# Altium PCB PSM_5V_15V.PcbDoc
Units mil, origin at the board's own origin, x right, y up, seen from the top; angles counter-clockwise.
Board outline 1150 x 1300 mil, 2 copper layers (Top Layer, Bottom Layer), stack 62 mil thick; 19 components, 10 nets, 41 pads, 8 vias.
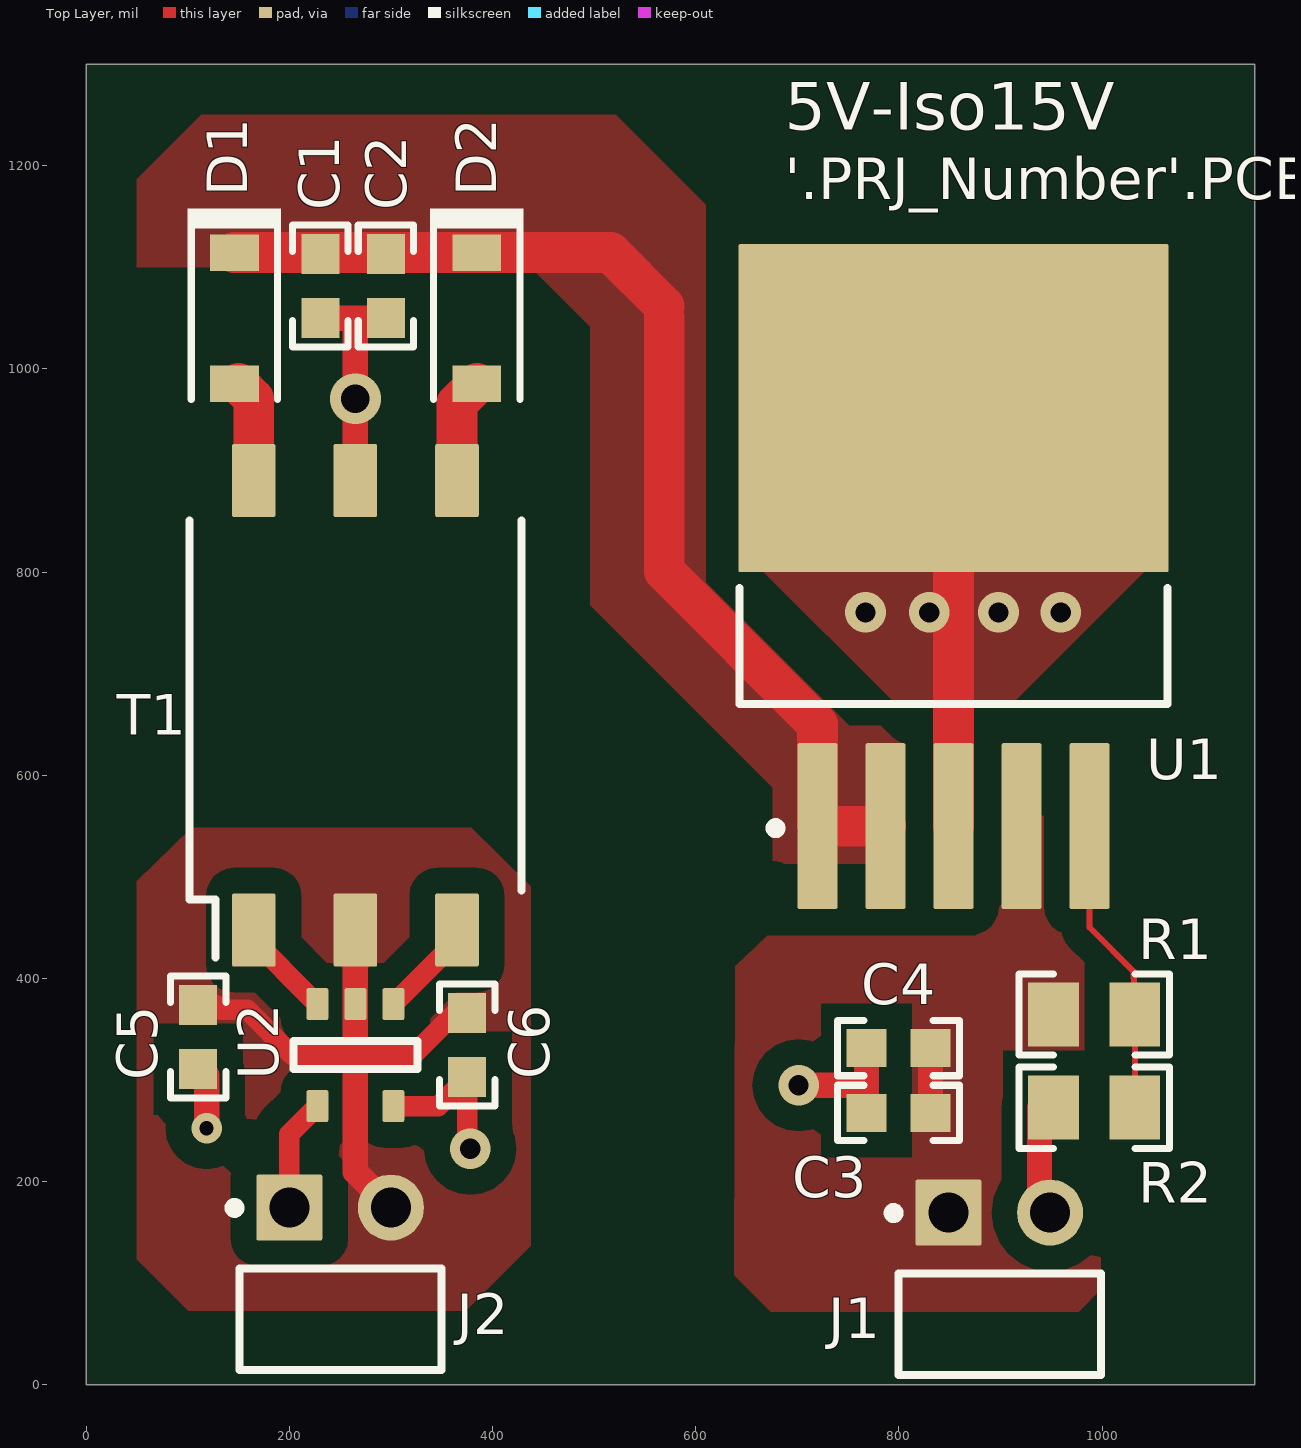
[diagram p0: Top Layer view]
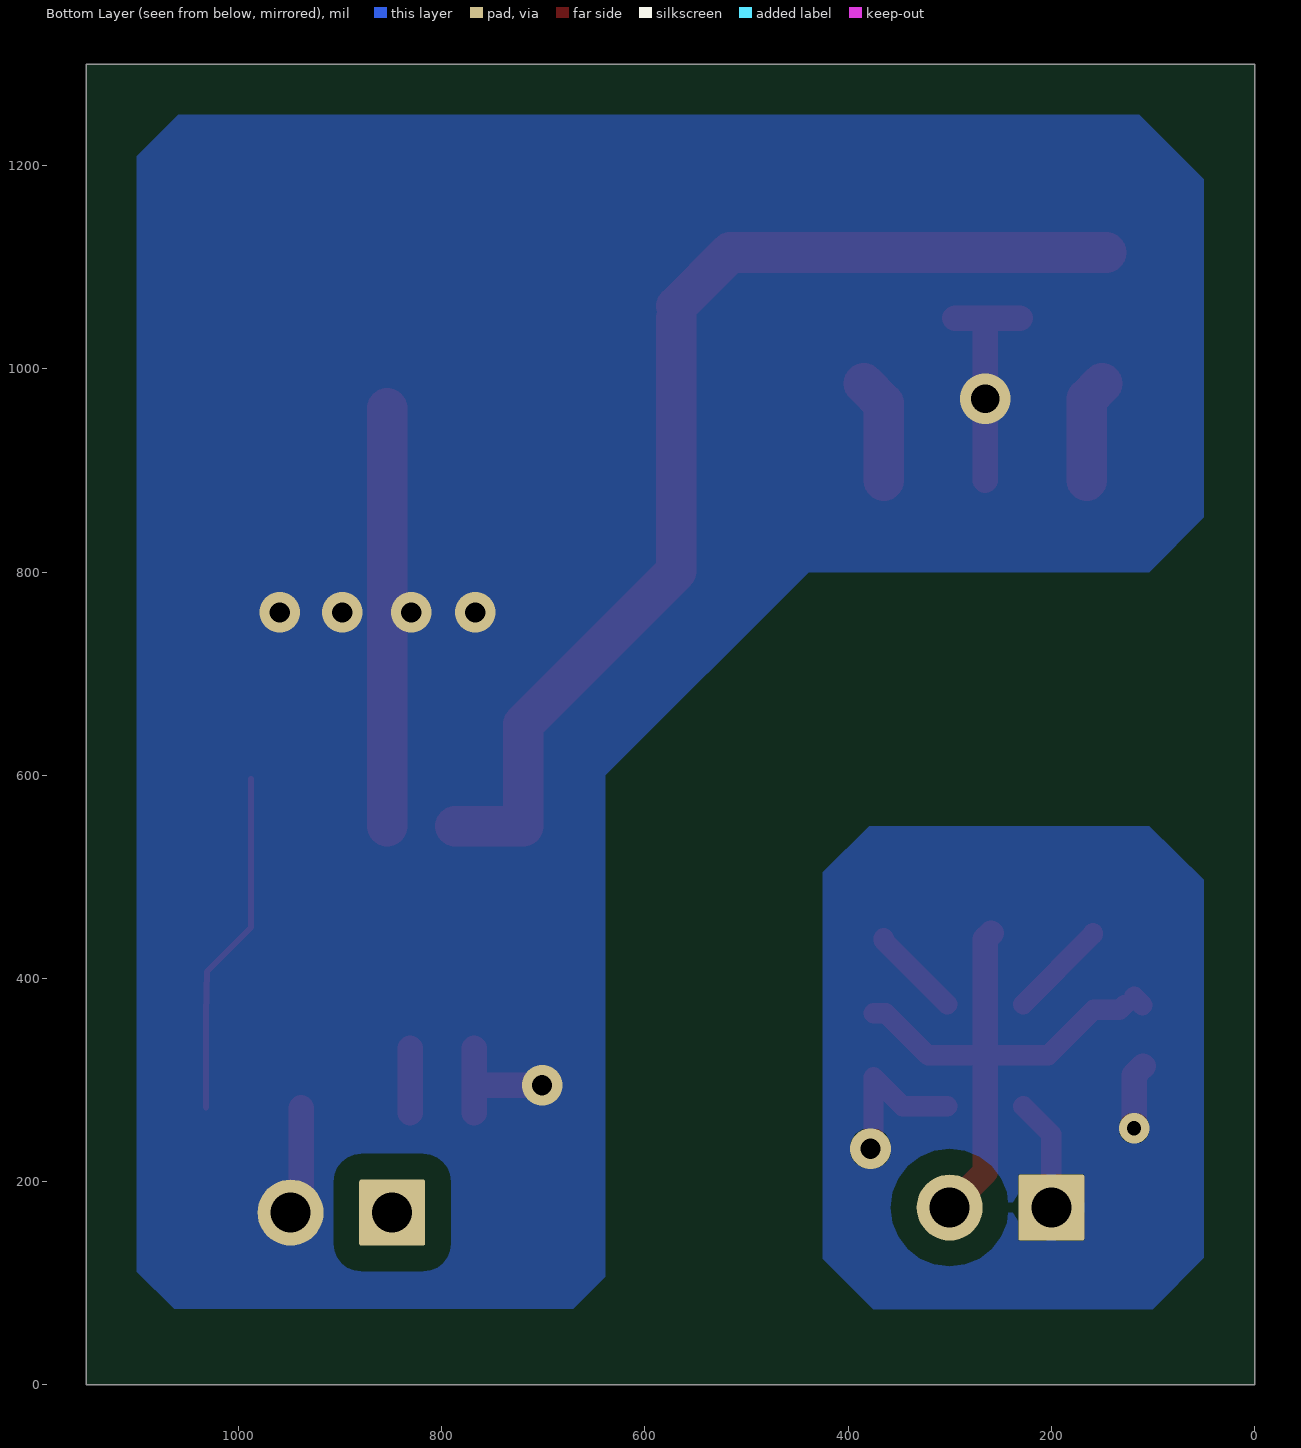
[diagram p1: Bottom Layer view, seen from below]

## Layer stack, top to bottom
Top Solder: solder mask 0.4, Solder Resist, Dk 3.5
Top Layer: signal copper 1.4
Dielectric1: core 59.2, FR-4, Dk 4.8
Bottom Layer: signal copper 1.4
Bottom Solder: solder mask 0.4, Solder Resist, Dk 3.5

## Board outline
0,0 1150,0 1150,1300 0,1300

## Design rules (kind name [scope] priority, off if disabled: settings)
AcuteAngle [All] p1: minimum=4.50000000000000E+0001 checktracksonly=FALSE
AssemblyTestPointUsage [All] p1: valid=2
BoardOutlineClearance BoardOutlineClearance_MountingHoles [OnCopper and InComponentClass('Mounting Holes')] p1: gap=39.37 ignorepadtopadclearanceinfootprint=FALSE
BoardOutlineClearance BoardOutlineClearance_Poly [OnCopper and IsPoly] p2: gap=25 ignorepadtopadclearanceinfootprint=FALSE
BoardOutlineClearance [OnCopper and Not InComponentClass('Logo') and not InComponentClass('FiducialMark') and not InRegion(1000,500,4000,800) and not InPoly] p3: gap=75 ignorepadtopadclearanceinfootprint=FALSE
Clearance Clearance_Keepouts [((IsTrack Or IsArc) And Not InPoly) And IsFree and IsKeepOut vs ((IsTrack Or IsArc) And Not InPoly) And IsFree and IsKeepOut] p1: gap=0 ignorepadtopadclearanceinfootprint=FALSE
Clearance Clearance_Poly [InPolygon] p2: gap=25 ignorepadtopadclearanceinfootprint=TRUE
Clearance Clearance_FiducialMark [IsKeepOut and InComponentClass('FiducialMark') vs IsPad and InComponentClass('FiducialMark')] p3: gap=0 ignorepadtopadclearanceinfootprint=FALSE
Clearance [All] p4: gap=7.87 ignorepadtopadclearanceinfootprint=TRUE
ComponentClearance ComponentClearance_MountingHoles_FiducialMarks [InComponentClass('Mounting Holes') vs InComponentClass('FiducialMark')] p1: gap=50 collisioncheckmode=3 verticalgap=10 showdistances=FALSE
ComponentClearance ComponentClearance_Shunt [InComponentClass('Header') vs InComponentClass('Shunt')] p2: gap=0 collisioncheckmode=3 verticalgap=0 showdistances=FALSE
ComponentClearance ComponentClearance_Logo [InComponentClass('Hardware')] p3: gap=20 collisioncheckmode=3 verticalgap=10 showdistances=FALSE
ComponentClearance ComponentClearance_ScrewToNut [(HasFootprint('NY PMS 440 0025 PH')) vs (HasFootprint('Keystone_1902C'))] p4: gap=5 collisioncheckmode=3 verticalgap=10 showdistances=FALSE
ComponentClearance ComponentClearance_MountingHoles [InComponentClass('Mounting Holes')] p5: gap=250 collisioncheckmode=3 verticalgap=100000 showdistances=FALSE
ComponentClearance ComponentClearance_SmallPassives [HasFootprint('0201*') or HasFootprint('0402*') or HasFootprint('0508') or HasFootprint('0603*') or HasFootprint('0612') or HasFootprint('0805*') or HasFootprint('0815*') or HasFootprint('0830*') or HasFootprint('1206*') or HasFootprint('1210*') or HasFootprint('1808*') or HasFootprint('1812*') or HasFootprint('1825*') or HasFootprint('2010*') or HasFootprint('2220*') or HasFootprint('2225*') or HasFootprint('2512*') or HasFootprint('2728*') or HasFootprint('3518*') vs HasFootprint('0201*') or HasFootprint('0402*') or HasFootprint('0508') or HasFootprint('0603*') or HasFootprint('0612') or HasFootprint('0805*') or HasFootprint('0815*') or HasFootprint('0830*') or HasFootprint('1206*') or HasFootprint('1210*') or HasFootprint('1808*') or HasFootprint('1812*') or HasFootprint('1825*') or HasFootprint('2010*') or HasFootprint('2220*') or HasFootprint('2225*') or HasFootprint('2512*') or HasFootprint('2728*') or HasFootprint('3518*')] p6: gap=14.96 collisioncheckmode=3 verticalgap=10 showdistances=FALSE
ComponentClearance ComponentClearance_THtoSMT [IsThruComponent vs IsSMTComponent] p7: gap=40 collisioncheckmode=3 verticalgap=30 showdistances=FALSE
ComponentClearance ComponentClearance_THtoTH [IsThruComponent vs IsThruComponent] p8: gap=30 collisioncheckmode=3 verticalgap=30 showdistances=FALSE
ComponentClearance [not InComponent('Logo2')] p9: gap=30 collisioncheckmode=3 verticalgap=10 showdistances=FALSE
DiffPairsRouting [All] p1: maxlimit=100 minlimit=10 mostfreqgap=10 toplayer_minwidth=15 toplayer_maxwidth=15 toplayer_prefwidth=15 bottomlayer_minwidth=15 bottomlayer_maxwidth=15 bottomlayer_prefwidth=15 maxuncoupledlength=1000
FabricationTestPointUsage TestPointUsage [All] p1: valid=2 allowmultiple=FALSE
FabricationTestpoint Testpoint [All] p1: side=3 testpointundercomponent=TRUE minsize=40 maxsize=100 preferedsize=60 minholesize=0 maxholesize=40 preferedholesize=32 testpointgrid=1 allowsidetop=TRUE allowsidebottom=TRUE usegrid=TRUE gridtolerance=0.01
FanoutControl Fanout_LCC [IsLCC] p1: bgadir=Out bgaviamode=Centered fanoutstyle=Auto fanoutdirection=Alternating viagrid=1 // Fanout_LCC (Default Rule)
FanoutControl Fanout_BGA [IsBGA] p2: bgadir=Out bgaviamode=Centered fanoutstyle=Auto fanoutdirection=Alternating viagrid=1 // Fanout_BGA (Default Rule)
FanoutControl Fanout_Default [All] p4: bgadir=Out bgaviamode=Centered fanoutstyle=Auto fanoutdirection=Alternating viagrid=1 // Fanout_Default (Default Rule)
FanoutControl Fanout_Small [(CompPinCount < 5)] p5: bgadir=Out bgaviamode=Centered fanoutstyle=Auto fanoutdirection=OutThenIn viagrid=1 // Fanout_Small (Default Rule)
HoleSize [All] p1: absolutevalues=TRUE maxlimit=251 minlimit=7.87 maxpercent=80.000 minpercent=20.000
MinimumAnnularRing MinimumAnnularRing_ThermalPadVias [IsVia and InAnyComponent] p1: minimumring=5.91
MinimumAnnularRing [All] p2: minimumring=7.87
MinimumSolderMaskSliver MinimumSolderMaskSliver_Logo [InComponentClass('Logo') vs InComponentClass('Logo')] p1: minsoldermaskwidth=0.7
MinimumSolderMaskSliver [All] p2: minsoldermaskwidth=3.94
PlaneConnect [All] p1: planeconnectstyle=Relief reliefexpansion=10 reliefentries=4 reliefconductorwidth=10 reliefairgap=10
PolygonConnect [All] p1: connectstyle=Direct reliefconductorwidth=10 reliefentries=4 polygonreliefangle="90 Angle" airgapwidth=10
RoutingVias ThermalPadVias [IsVia and InAnyComponent] p1: holewidth=7.87 width=19.68 viastyle="Through Hole" minholewidth=7.87 minwidth=19.68 maxholewidth=12.99 maxwidth=23.62
RoutingVias [All] p2: holewidth=16 width=34 viastyle="Through Hole" minholewidth=7.87 minwidth=26 maxholewidth=40 maxwidth=65
SilkToBoardRegionClearance [Not ((IsComment or IsDesignator) And (Hide <> 'False')) and not InRegion(1000,500,4000,800)] p1:
SilkToSilkClearance SilkToSilkClearance_Pb-FreeLogo [(HasFootprint('Pb-Free_Overlay_Medium') OR HasFootprint('Pb-Free_Overlay_Small')) vs (HasFootprint('Pb-Free_Overlay_Medium') OR HasFootprint('Pb-Free_Overlay_Small'))] p1: silktosilkclearance=0
SilkToSilkClearance [All] p2: silktosilkclearance=3.94
SilkToSolderMaskClearance SilkToComponentPadClearance [(IsPad or IsFill or IsRegion) and InAnycomponent and not ((InComponent('D1') OR InComponent('D2')))] p1: minsilkscreentomaskgap=5 clearancetoexposedcopper=TRUE
SilkToSolderMaskClearance "Silk to Solder Mask Opening" [not ((InComponent('D1') OR InComponent('D2')))] p2: minsilkscreentomaskgap=3.94 clearancetoexposedcopper=FALSE
SolderMaskExpansion [All] p1: expansion=1.97
UnRoutedNet [All] p1: checkbadconnections=TRUE
Width [All] p1: maxlimit=100 minlimit=6 preferedwidth=10 checkconnectedcopper=TRUE
14 further rules are at their usual default settings.

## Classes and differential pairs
component class AssemblyNote: ZZ1 ZZ2 ZZ3 ZZ4

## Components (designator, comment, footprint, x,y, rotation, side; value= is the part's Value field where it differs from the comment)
C1 "C1608X5R1E106M080AC" 0603 230.53,1081.5 r90 top value=10uF
C2 "GCM188R71H103KA37D" 0603 295,1081.56 r270 top value=0.01uF
C3 "C1608X5R1E106M080AC" 0603 799.55,267.72 r180 top value=10uF
C4 "GCM188R71H103KA37D" 0603 799.55,331.57 r180 top value=0.01uF
C5 "GCM188R71C105KA64D" 0603 110.26,342.32 r270 top value=1uF
C6 "CGA3E2X7R1H104K080AA" 0603 375,334.45 r270 top value=0.1uF
D1 "MBR0540T1G" SOD-123 145.93,1050.07 r270 top value=40V
D2 "MBR0540T1G" SOD-123 384.53,1050.07 r270 top value=40V
J1 "TSW-102-08-G-S-RA" TSW-102-08-G-S-RA 898.72,169.61 r0 top
J2 "TSW-102-08-G-S-RA" TSW-102-08-G-S-RA 250,174.61 r0 top
R1 "ERJ-6ENF1152V" 0805_HV 992.19,364.55 r180 top value=11.5k
R2 "ERJ-6ENF1021V" 0805_HV 992.19,272.87 r0 top value=1.02k
T1 "750316818" Wurth_750316029 265.01,668.97 r90 top value=94uH
U1 "TL1963AQKTTRQ1" KTT0005A_N 853.72,796.06 r90 top
U2 "SN6501QDBVRQ1" DBV0005A_L 265.01,324.61 r270 top
ZZ1 "This Assembly Note is for PCB labels only" AssemblyNoteLabel 60,1663 r0 top
ZZ2 "These assemblies are ESD sensitive, ESD precautions shall be observed." AssemblyNote 60,1554.11 r0 top
ZZ3 "These assemblies must be clean and free from flux and all contaminants. Use of no clean flux is not acceptable." AssemblyNote 60,1465.56 r0 top
ZZ4 "These assemblies must comply with workmanship standards IPC-A-610 Class 2, unless otherwise specified." AssemblyNote 60,1377 r0 top

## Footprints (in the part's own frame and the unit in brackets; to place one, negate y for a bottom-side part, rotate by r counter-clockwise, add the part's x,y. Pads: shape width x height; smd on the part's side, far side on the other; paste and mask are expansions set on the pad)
0603 [mm] "0603 from SM-752 data"
  rect 1x0.95 smd: 1(-0.8,0) 2(0.8,0)
  silkscreen extent -1.52,-0.69 1.52,0.69, body extent -0.87,-0.47 0.87,0.47, height 1
0805_HV [mil] "0805 with 30mil clearance between pads"
  rect 50x63 smd: 1(-40,0) 2(40,0)
  silkscreen extent -74,-40 74,40, body extent -43,-29 43,29, height 57
AssemblyNote [mil] "Assembly Note"
AssemblyNoteLabel [mil] "Assembly Note for PCB Labels"
DBV0005A_L [mm] "SOT23, 5-Leads, Body 2.9x1.6mm, Pitch 0.95mm, Lead Span 2.8mm, IPC High Density"
  rrect18% 0.8x0.55 smd: 1(-1.275,0.95) 2(-1.275,0) 3(-1.275,-0.95) 4(1.275,-0.95) 5(1.275,0.95)
  silkscreen extent -0.35,-1.55 0.35,1.55, body extent -1.42,-1.46 1.42,1.46, height 1.09
KTT0005A_N [mm] "D2-PAK, 6-Leads, Body 8.9x10.2mm, Pitch 1.7mm, Lead Span 15.2mm, IPC Medium Density"
  rrect10% 4.15x1 smd: 1(-6.25,3.4) 2(-6.25,1.7) 3(-6.25,0) 4(-6.25,-1.7) 5(-6.25,-3.4)
  rrect1% 8.2x10.75 smd: 6(4.2,0)
  silkscreen extent -6.42,-5.35 -0.3,5.35, body extent -7.63,-5.08 7.63,5.08, height 4.83
SOD-123 [mm] "On Semi recommended land pattern"
  rect 0.915x1.22 smd: 1(-1.637,0) 2(1.637,0)
  silkscreen extent -2.74,-1.17 2.03,1.17, body extent -1.93,-0.9 1.93,0.9, height 1.35
TSW-102-08-G-S-RA [mm] "Samtec Right Angle Header"
  rrect6% 1.65x1.65 hole 1: 1(-1.27,0)
  round 1.65 hole 1: 2(1.27,0)
  silkscreen extent -2.76,-4.06 2.54,0.11, body extent -2.54,-9.91 2.54,0.32, height 3.05
Wurth_750316029 [mm] "SMD, 6-Leads, Body 9.25x8.3mm, Pitch 2.54mm"
  rrect9% 1.83x1.09 smd: 1(-5.62,2.54) 2(-5.62,0) 3(-5.62,-2.54) 4(5.62,-2.54) 5(5.62,0) 6(5.62,2.54)
  silkscreen extent -6.3,-4.15 4.62,4.15, body extent -4.62,-4.15 4.62,4.15, height 4.11

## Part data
C1 C3: library part CMP-0007007-5, "CAP, CERM, 10 uF, 25 V, +/- 20%, X5R, 0603", Cap_Case=0603, Manufacturer=TDK, Supplier Part Number 1=445-9015-1-ND, TempCo=X5R, Tolerance_%=20%, Value1="0.004639 ohm", Value2=25V, ValueDisplayed=10uF
C2 C4: library part CMP-0007143-4, "CAP, CERM, 0.01 uF, 50 V, +/- 10%, X7R, AEC-Q200 Grade 1, 0603", Cap_Case=0603, Manufacturer=MuRata, Supplier Part Number 1=490-4778-1-ND, TempCo=X7R, Tolerance_%=10%, Value1=Unknown, Value2=50V, ValueDisplayed=0.01uF
C5: library part CMP-0007136-5, "CAP, CERM, 1 uF, 16 V, +/- 10%, X7R, AEC-Q200 Grade 1, 0603", Cap_Case=0603, Manufacturer=MuRata, Supplier Part Number 1=490-5241-6-ND, TempCo=X7R, Tolerance_%=10%, Value1=Unknown, Value2=16V, ValueDisplayed=1uF
C6: library part CMP-0007078-4, "CAP, CERM, 0.1 uF, 50 V, +/- 10%, X7R, AEC-Q200 Grade 1, 0603", Cap_Case=0603, Manufacturer=TDK, Supplier Part Number 1=445-5666-1-ND, TempCo=X7R, Tolerance_%=10%, Value1="0.0296 ohm", Value2=50V, ValueDisplayed=0.1uF
D1 D2: library part CMP-0028526-2, "Diode, Schottky, 40 V, 0.5 A, SOD-123", Manufacturer="ON Semiconductor", Value1=0.5A, Value2=0.51V
J1 J2: library part CMP-0055976-1, "Header, 100mil, 2x1, Gold, R/A, TH", Color=Black, Current_A=6.3A, Manufacturer=Samtec, Supplier Part Number 1=SAM1039-02-ND, Voltage_V=550V
R1: library part CMP-0021540-3, "RES, 11.5 k, 1%, 0.125 W, AEC-Q200 Grade 0, 0805", Manufacturer=Panasonic, Power_W=125mW, Supplier Part Number 1=P11.5KCCT-ND, TempCo="100 ppm/C", Tolerance_%=1%, Value2=0.125W, Value_Code=11k5, ValueDisplayed=11.5k
R2: library part CMP-0021523-3, "RES, 1.02 k, 1%, 0.125 W, AEC-Q200 Grade 0, 0805", Manufacturer=Panasonic, Power_W=125mW, Supplier Part Number 1=P1.02KCCT-ND, TempCo="100 ppm/C", Tolerance_%=1%, Value2=0.125W, Value_Code=1k02, ValueDisplayed=1.02k
T1: library part CMP-0067601-1, "Transformer, 94 uH, SMT", Manufacturer="Wurth Elektronik", ValueDisplayed=94µH
U1: library part CMP-0036893-1, "Single Output Fast Transient Response LDO, 1.5 A, Adjustable 1.21 to 20 V Output, 2.1 to 20 V Input, 5-pin DDPAK (KTT), -40 to 125 degC, Green (RoHS & no Sb/Br)", Manufacturer="Texas Instruments"
U2: library part CMP-0076093-1, "Automotive Low-Noise 350 mA, 410 kHz Transformer Driver, DBV0005A (SOT-23-5)", Alternate Manufacturer="Texas Instruments"
ZZ1: library part CMP-0003616-3
ZZ2: library part CMP-0077236-1
ZZ3: library part CMP-0077237-1
ZZ4: library part CMP-0077238-1

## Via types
v1: diameter 40, hole 20, Top Layer to Bottom Layer, 6 vias
v2: diameter 50, hole 28, Top Layer to Bottom Layer, 1 vias
v3: diameter 30, hole 14, Top Layer to Bottom Layer, 1 vias

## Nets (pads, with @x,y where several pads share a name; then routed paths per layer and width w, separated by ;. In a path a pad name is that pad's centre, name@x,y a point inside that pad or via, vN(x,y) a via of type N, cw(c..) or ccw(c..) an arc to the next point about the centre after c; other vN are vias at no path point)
5V: C5.1 C6.1 J2.2 T1.2 U2.2 | length 583
  Top Layer w20: C5.1 C5.1@118.53,382.09 ; C5.1@128.29,373.82 132.9,369.2 158.46,369.2 203.06,324.61 265.01,324.61 321.46,324.61 362.8,365.94 C6.1
  Top Layer w25: T1.2@259,444.74 265.01,438.74 U2.2 265.01,324.61 265.01,209.6 J2.2
15V: C3.1 C4.1 J1.1 R1.2 U1.4 | length 63.9
  Top Layer w25: C3.1 C4.1
DGND: C5.2 C6.2 J2.1 U2.4 U2.5 | length 332
  Top Layer w20: J2.1 200,246.81 U2.4 ; U2.5 346.46,274.41 C6.2 375,235.58 v1(378,232.58)
  Top Layer w25: C5.2@109.59,313.78 118.53,304.83 v3(118.53,252.72)
NetC1_2: C1.2 C2.1 D1.1 D2.1 U1.1 U1.2 | length 1074.5
  Top Layer w40: D1.1 D2.1 516.19,1114.53 569.03,1061.7 ; 569.03,1050.07 569.03,801.05 719.87,650.21 U1.1 U1.2
NetD1_2: D1.2 T1.6 | length 101.6
  Top Layer w40: D1.2@150,985.6 165.01,970.59 T1.6
NetD2_2: D2.2 T1.4 | length 103.5
  Top Layer w40: T1.4 365.01,966.07 D2.2
NetR1_1: R1.1 R2.2 U1.5 | length 341.4
  Top Layer w6: U1.5@987.58,596.19 U1.5 987.58,450.42 1031.11,406.89 R1.1 R2.2
NetT1_1: T1.1 U2.3 | length 98.4
  Top Layer w20: T1.1@159,444.74 159,443.4 U2.3
NetT1_3: T1.3 U2.1 | length 90.7
  Top Layer w20: U2.1 365.01,437.4 T1.3@365.01,439.54
RSLVR_GND: C1.1 C2.2 C3.2 C4.2 J1.2 R2.1 T1.5 U1.3 U1.6 | length 915.2
  Top Layer w25: T1.5 v2(265.01,970.59) 265.01,1047.21 267.8,1050 C1.1 230.6,1050.07 C2.2 ; v1(701.23,294.92) 760.64,294.92 767.53,301.8 767.79,302.07 768.05,301.8 ; C3.2 768.05,301.8 ; C4.2 768.05,301.8 ; R2.1@938.37,272.64 938.37,179.96 J1.2
  Top Layer w40: U1.3 U1.6
  other v1: 767.16,760.34 829.85,760.34 897.94,760.34 959.34,760.34

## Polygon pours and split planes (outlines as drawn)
RSLVR_GND on Bottom Layer "BOTTOM_LAYER_RSLVR_GND_P004" (solid, remove dead copper, pour order 4): 113.25,1250 50,1186.75 50,853.8 103.8,800 439,800 638.95,600.05 638.95,106.55 670.64,75 1063.37,75 1100,111.63 1100,1209.54 1059.54,1250
DGND on Bottom Layer "BOTTOM_LAYER_DGND_P000" (solid, remove dead copper, pour order 0): 50,497.05 50,125 100.39,74.61 375.21,74.61 425,124.4 425,504.71 378.99,550 103.8,550
15V on Top Layer "TOP_LAYER_15V_P014" (solid, remove dead copper, pour order 14): 638.95,412.02 638.01,108.08 673.87,72.22 976.98,72.22 998.72,93.97 998.72,560 910.96,560 910.96,485.66 875.49,442.04 670.24,442.04
RSLVR_GND on Top Layer "TOP_LAYER_RSLVR_GND_P018" (solid, remove dead copper, pour order 18): 651.49,815.75 797.24,670 910.96,670 1056.71,815.75
NetC1_2 on Top Layer "TOP_LAYER_NETC1_2_P016" (solid, remove dead copper, pour order 16): 50,1186.75 50,1100 437.5,1100 495.96,1041.53 495.96,767.6 675.88,587.69 675.88,512.92 804.6,512.92 804.6,640 794.94,648.96 751.04,648.96 609.74,790.26 609.74,1161.67 521.41,1250 113.25,1250
5V on Top Layer "TOP_LAYER_5V_P012" (solid, remove dead copper, pour order 12): 50,495.59 50,123.55 100.39,73.15 373.75,73.15 437.5,136.89 437.5,490.96 378.99,548.55 103.8,548.55

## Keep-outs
Keep-Out Layer:
  text ".Layer_Name" at 577,-858.49 h60

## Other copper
Top Layer:
  text ".Layer_Name" at 577,-858.49 h60
Bottom Layer:
  text ".Layer_Name" at 577,-858.49 h60

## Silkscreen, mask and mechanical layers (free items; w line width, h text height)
Top Overlay:
  text "5V-Iso15V" at 687.58,1220 h80
  text "'.PRJ_Number'.PCB_Rev" at 687.58,1153.07 h70
  text ".Layer_Name" at 577,-858.49 h60
Bottom Overlay:
  text ".Layer_Name" at 577,-858.49 h60
Top Paste:
  text ".Layer_Name" at 577,-858.49 h60
Bottom Paste:
  text ".Layer_Name" at 577,-858.49 h60
Top Solder:
  text ".Layer_Name" at 577,-858.49 h60
  text ".Layer_Name" at 577,-858.49 h60
Bottom Solder:
  text ".Layer_Name" at 577,-858.49 h60
Drill Guide:
  text ".Layer_Name" at 577,-858.49 h60
M1 Board Outline:
  the board outline again, w10
  text ".Layer_Name" at 577,-858.49 h60
M2 Board Dimensions:
  rectangle: 0,-275 125,-150
  rectangle: 125,-400 500,-275
  lines w7: 0,-275 1000,-275 ; 125,-400 125,-150 ; 250,-400 250,-150 ; 500,-400 500,-150 ; 750,-400 750,-150 ; 0,-400 1000,-400 1000,-150 0,-150 0,-400
  text ".Layer_Name" at 577,-858.49 h60
M3 3D STEP Top:
  text ".Layer_Name" at 577,-858.49 h60
M4 3D STEP Bottom:
  text ".Layer_Name" at 577,-858.49 h60
M5 Assembly Top:
  lines w10: -292,-930.17 6308,-930.17 ; -292,-726.83 6310,-726.83 ; -292,-523.5 -292,-1133.5 3713,-1133.5 6310,-1133.5 6310,-523.5 -291.5,-523.5 -291.5,-1133.5 1284,-1133.5 ; 2173,-1133.5 2173,-523.5 ; 3440,-726.83 3440,-523.5 ; 4280,-726.83 4280,-523.5 ; 4902,-1140 4902,-937.17
  text "COMPONENTS MARKED 'DNP' SHOULD NOT BE POPULATED." at 1153.5,-318.5 h60
  text "ASSEMBLY VARIANT:" at 1153,-434 h60
  text ".VariantName" at 2189,-434 h60
  text "PCB VIEWED FROM TOP SIDE" at -228.5,-655.67 h60
  text "BOARD #:" at 2248,-655.67 h60
  text ".PRJ_Number" at 2793.5,-655.67 h60
  text "REV:" at 3638,-655.67 h60
  text ".PCB_Rev" at 3929.5,-655.67 h60
  text "SVN REV:" at 4476,-655.67 h60
  text ".VersionControl_RevNumber" at 4982,-655.67 h60
  text "TID #:" at 2248,-859 h60
  text ".TID" at 2793.5,-859 h60
  text "PLOT NAME =" at -228.5,-1064.34 h60
  text ".plot_File_Name" at 577,-1064.34 h60
  text "GENERATED    :" at 2250,-1064.34 h60
  text ".Print_Date" at 3119.5,-1064.34 h60
  text ".Print_Time" at 3848.5,-1064.34 h60
  text "TEXAS INSTRUMENTS" at 5113,-1064.34 h60
M6 Assembly Bottom:
  lines w10: -292.5,-727.33 6309.5,-727.33 ; -290.5,-930.67 6309.5,-930.67 ; 1115.5,-1140.5 1115.5,-937.67 ; 1737.5,-727.33 1737.5,-524 ; 2577.5,-727.33 2577.5,-524 ; 3844.5,-1134 3844.5,-524 ; 4733.5,-1134 6309,-1134 6309,-524 -292.5,-524 -292.5,-1134 2304.5,-1134 6309.5,-1134 6309.5,-524
  text "COMPONENTS MARKED 'DNP' SHOULD NOT BE POPULATED." at 6102,-318 h60
  text ".VariantName" at 5058,-434 h60
  text "ASSEMBLY VARIANT:" at 6097,-434 h60
  text ".VersionControl_RevNumber" at 1035.5,-656.17 h60
  text "SVN REV:" at 1541.5,-656.17 h60
  text ".PCB_Rev" at 2088,-656.17 h60
  text "REV:" at 2379.5,-656.17 h60
  text ".PRJ_Number" at 3224,-656.17 h60
  text "BOARD #:" at 3769.5,-656.17 h60
  text "PCB VIEWED FROM BOTTOM SIDE" at 6246,-656.17 h60
  text ".TID" at 3224,-859.5 h60
  text "TID #:" at 3769.5,-859.5 h60
  text "TEXAS INSTRUMENTS" at 904.5,-1064.84 h60
  text ".Print_Time" at 2169,-1064.84 h60
  text ".Print_Date" at 2898,-1064.84 h60
  text "GENERATED    :" at 3767.5,-1064.84 h60
  text ".plot_File_Name" at 5440.5,-1064.84 h60
  text "PLOT NAME =" at 6246,-1064.84 h60
M9 Title Sheet:
  drawing of 57 lines, arcs and shapes, not listed
  text "1" at 739.84,8036.5 h70
  text "2" at 3235.5,8036.5 h70
  text "3" at 5724.84,8036.5 h70
  text "4" at 8231.51,8036.5 h70
  text "5" at 10730.5,8036.5 h70
  text "6" at 13235.5,8036.5 h70
  text "A" at -416.5,6893.5 h70
  text "A" at 14383.5,6893.5 h70
  text "B" at -416.5,4513.5 h70
  text "B" at 14383.5,4513.5 h70
  text "C" at -416.5,2138.5 h70
  text "C" at 14383.5,2138.5 h70
  text "PROJECT TITLE:" at 11343.5,277.5 h45
  text ".PRJ_Title" at 11393.5,144.17 h70
  text "DESIGNED FOR:" at 11343.5,-23.5 h45
  text ".PRJ_Customer" at 11393.5,-163.5 h70
  text "D" at -416.5,-231.5 h70
  text "D" at 14383.5,-231.5 h70
  text "FILE NAME:" at 11343.5,-323.5 h45
  text ".PCB_File_Name_No_Path" at 11393.5,-443.5 h70
  text "Texas Instruments (TI) and/or its licensors do not warrant the accuracy or completeness of this specification" at 6374,-605.34 h45
  text "ENGINEER:" at 11343.5,-613.5 h45
  text "LAYOUT BY:" at 12848.5,-613.5 h45
  text "or any information contained therein. TI and/or its licensors do not warrant that this design will meet" at 6329.01,-718 h45
  text ".PRJ_Engineer" at 11393.5,-768.49 h70
  text ".PCB_Layout" at 12899,-768.49 h70
  text "the specifications, will be suitable for your application or fit for any particular purpose, or will operate in" at 6329.01,-830.67 h45
  text ".Layer_Name" at 577,-858.49 h60
  text "ALTIUM DESIGNER VERSION:" at 12848.5,-923.5 h45
  text "an implementation. TI and/or its licensors do not warrant that the design is production worthy. You should" at 6329.01,-943.33 h45
  text "completely validate and test your design implementation to confirm the system functionality for your application." at 6374,-1056 h45
  text ".print_Scale" at 11393.5,-1056.83 h70
  text ".Application_BuildNumber" at 12899,-1056.83 h70
  text "1" at 739.84,-1263.5 h70
  text "2" at 3235.5,-1263.5 h70
  text "3" at 5724.84,-1263.5 h70
  text "4" at 8231.51,-1263.5 h70
  text "5" at 10730.5,-1263.5 h70
  text "6" at 13235.5,-1263.5 h70
M10 Fab Notes:
  drawing of 189 lines, arcs and shapes, not listed
  text "DESIGN INFORMATION" at 12382.02,6356.17 h60
  text "MIN. TRACK WIDTH:" at 11737.46,6224.05 h60
  text "8" at 12833.7,6224.05 h60
  text "MIL" at 12988.46,6224.05 h60
  text "MIN. CLEARANCE:" at 11737.46,6099.92 h60
  text "0.2" at 12773.7,6099.93 h60
  text "mm" at 12988.46,6099.92 h60
  text "MIN. VIA PAD SIZE:" at 11737.46,5975.8 h60
  text "24" at 12803.71,5975.8 h60
  text "MIL" at 12988.46,5975.8 h60
  text "0.05mm (2MIL)" at 12432.46,5845.9 h60
  text "MINIMUM ANNULAR RING" at 11408.23,5837.67 h60
  text "EXTERNAL" at 13140.46,5837.67 h60
  text "PER" at 11608.23,5727.55 h60
  text "IPC-D-275 CLASS 2 LEVEL C" at 11828.23,5727.54 h60
  text "MIL, HOLES" at 13316.46,5627.07 h60
  text "+/-" at 12924,5618.48 h60
  text "+/-" at 13778,5618.48 h60
  text "REGISTRATION TOLERANCES:" at 11408.23,5617.42 h60
  text "METAL" at 12608,5617.42 h60
  text "5" at 13184.2,5617.42 h60
  text "3" at 14017.2,5617.42 h60
  text "MIL" at 14133.46,5617.42 h60
  text "HOLE SIZE TOLERANCE (UNLESS OTHERWISE SPECIFIED):" at 11408.23,5519.1 h60
  text "+/-" at 13778,5516.23 h60
  text "3" at 14017.2,5515.17 h60
  text "MIL" at 14133.46,5515.17 h60
  text "MATERIAL:" at 11333.46,5377.52 h60
  text "FR-4 High Tg" at 12319.9,5249 h60
  text "X" at 12175.46,5241.01 h60
  text "FR-408" at 11754.46,5236.49 h60
  text "OTHER" at 13242.46,5236.49 h60
  text "62 MIL (1.6mm) +/-10%" at 12074.56,5093.46 h60
  text "X" at 11954.46,5091.01 h60
  text "THICKNESS:" at 11408.23,5085.24 h60
  text "OTHER" at 13359.46,5085.24 h60
  text "TOLERANCE:" at 11408.23,4946.92 h60
  text "X" at 12256.46,4946.92 h60
  text "ANSI IPC-6012 TYPE 3 CLASS 2" at 12434.48,4946.92 h60
  text "OTHER +/-" at 12434.46,4802.73 h60
  text "BOW & TWIST:" at 11408.23,4657.54 h60
  text "X" at 12256.46,4657.54 h60
  text "ANSI IPC-6012 TYPE 3 CLASS 2" at 12434.48,4657.54 h60
  text "OTHER +/-" at 12434.46,4510.85 h60
  text "DRILLING:" at 11333.46,4380.23 h60
  text "NC_DRILL FILES" at 13094.46,4275.04 h60
  text "REFERENCE:" at 11408.23,4271.1 h60
  text "X" at 12065.46,4271.01 h60
  text "AS SHOWN" at 12243.46,4271.1 h60
  text "X" at 12966.46,4271.1 h60
  text "OTHER" at 13392.46,4128.85 h60
  text "PTH COPPER THICKNESS:" at 11407.91,4125.32 h60
  text "X" at 12547.14,4125.32 h60
  text "20-30 um" at 12675.14,4125.32 h60
  text "BOARD FINISH:" at 11333.46,3977.73 h60
  text "SILKSCREEN:" at 11488.68,3867.6 h60
  text "X" at 12446.46,3867.6 h60
  text "TOP" at 12563.46,3867.6 h60
  text "BOTTOM" at 13074.46,3867.6 h60
  text "SILKSCREEN COLOR:" at 11488.68,3712.41 h60
  text "X" at 12445.46,3712.41 h60
  text "WHITE" at 12563.46,3712.41 h60
  text "OTHER" at 13074.46,3712.41 h60
  text "X" at 12576.46,3568.96 h60
  text "GREEN" at 12694.46,3568.96 h60
  text "OTHER" at 13312.46,3568.96 h60
  text "SOLDER RESIST COLOR:" at 11488.68,3562.1 h60
  text "X" at 12576.46,3414.71 h60
  text "MATTE" at 12694.46,3414.71 h60
  text "SEMI-GLOSS" at 13312,3414.07 h60
  text "IMMERSION GOLD (ENIG)" at 12394.46,3241.94 h60
  text "ENEPIG" at 13732,3234.72 h60
  text "SURFACE FINISH:" at 11333.46,3233.72 h60
  text "IMM. TIN/SILVER OR EQUIV" at 11663,3096.4 h60
  text "X" at 11520,3095 h60
  text "OTHER" at 13094.46,3092.47 h60
  text "ARRAY/PANEL:" at 11333.46,2937.09 h60
  text "CUT AND TRIM PER M1 BOARD OUTLINE" at 12394.46,2928.87 h60
  text "N.C. ROUTE" at 12394.46,2792.9 h60
  text "X" at 13082.46,2792.9 h60
  text "V. SCORE" at 13260.46,2792.9 h60
  text "CERTIFICATION:" at 11333.46,2663.77 h60
  text "MATERIALS AND WORKMANSHIP FOR ALL PCBS" at 12058.46,2663.77 h60
  text "TO MEET OR EXCEED THE REQUIREMENTS OF:" at 12058.46,2569.71 h60
  text "X" at 11695.97,2441.08 h60
  text "ANSI IPC-A-600F CLASS ->" at 11823.96,2441.08 h60
  text "X" at 13471.97,2441.08 h60
  text "2" at 13581.96,2441.08 h60
  text "1" at 13266.96,2439.58 h60
  text "3" at 13935.96,2439.58 h60
  text "X" at 12507.97,2293.39 h60
  text "RoHS" at 12635.96,2293.39 h60
  text "OTHER" at 13280.36,2293.39 h60
  text "PER ORDER" at 13677.42,2293.39 h60
  text "ALL BOARDS MUST MEET OR EXCEED UL94-V0 REQUIREMENTS." at 11361,2139.57 h60
  text "PCB MUST BEAR THE UL94V-0 UL REGISTERED MATERIAL ID NUMBER" at 11361,2023.5 h60
  text "ADDITIONAL REQUIREMENTS:" at 11333.46,1854.08 h60
  text "MICROSECTION:" at 11408.23,1746.95 h60
  text "YES" at 12313.96,1746.95 h60
  text "X" at 12601,1602.62 h60
  text "REQUIRED" at 13175.46,1602.62 h60
  text "BARE BOARD ELEC. TEST:" at 11408.23,1599.76 h60
  text "NONE" at 12713.96,1599.76 h60
  text "PER ORDER" at 13767.46,1599.76 h60
  text "XX MIL VIAS REQUIRE NON-CONDUCTIVE FILL AND PLANARIZE" at 11576.38,1394.82 h59
  text "XX MIL VIAS REQUIRE CONDUCTIVE FILL AND PLANARIZE" at 11584.38,1290.84 h60
  text "OUTER XX MIL TRACES REQUIRE 50 OHM SINGLE-ENDED IMPEDANCE" at 11583.39,1127.46 h58
  text "LAYER 2 & 3 (INNER LAYERS) XX MIL WIDE, XX MIL SPACE / TRACES REQUIRE 100 OHM DIFFERENTIAL IMPEDANCE" at 11575.39,891.74 h60
  text ".Layer_Name" at 577,-858.49 h60
M11 Gerber Information:
  lines w10: -292,-930.17 6308,-930.17 ; -292,-726.83 6310,-726.83 ; -292,-523.5 -292,-1133.5 3713,-1133.5 6310,-1133.5 6310,-523.5 -291.5,-523.5 -291.5,-1133.5 1284,-1133.5 ; 2173,-1133.5 2173,-523.5 ; 3440,-726.83 3440,-523.5 ; 4280,-726.83 4280,-523.5 ; 4902,-1140 4902,-937.17
  text "ALL ARTWORK VIEWED FROM TOP SIDE" at -228.5,-655.67 h60
  text "BOARD #:" at 2248,-655.67 h60
  text ".PRJ_Number" at 2793.5,-655.67 h60
  text "REV:" at 3638,-655.67 h60
  text ".PCB_Rev" at 3929.5,-655.67 h60
  text "SVN REV:" at 4476,-655.67 h60
  text ".VersionControl_RevNumber" at 4982,-655.67 h60
  text "LAYER NAME =" at -228.5,-858.49 h60
  text "TID #:" at 2248,-859 h60
  text ".TID" at 2793.5,-859 h60
  text "PLOT NAME =" at -228.5,-1064.34 h60
  text ".plot_File_Name" at 577,-1064.34 h60
  text "GENERATED    :" at 2250,-1064.34 h60
  text ".Print_Date" at 3119.5,-1064.34 h60
  text ".Print_Time" at 3848.5,-1064.34 h60
  text "TEXAS INSTRUMENTS" at 5113,-1064.34 h60
M12 Stackup:
  drawing of 191 lines, arcs and shapes, not listed
  text "Layer" at 9811.59,7559.94 h60
  text "Name" at 10221.51,7559.94 h60
  text "Material" at 11151.25,7559.94 h60
  text "Thickness" at 12011.02,7559.94 h60
  text "Constant" at 12660.85,7559.94 h60
  text "Board Layer Stack" at 13230.71,7559.94 h60
  text "1" at 9811.59,7439.94 h60
  text "Top Overlay" at 10221.51,7439.94 h60
  text "2" at 9811.59,7319.94 h60
  text "Top Solder" at 10221.51,7319.94 h60
  text "Solder Resist" at 11151.25,7319.94 h60
  text "0.40mil" at 12011.02,7319.94 h60
  text "3.5" at 12660.85,7319.94 h60
  text "3" at 9811.59,7199.94 h60
  text "Top Layer" at 10221.51,7199.94 h60
  text "Copper" at 11151.25,7199.94 h60
  text "1.40mil" at 12011.02,7199.94 h60
  text "4" at 9811.59,7079.94 h60
  text "Dielectric1" at 10221.51,7079.94 h60
  text "FR-4" at 11151.25,7079.94 h60
  text "59.20mil" at 12011.02,7079.94 h60
  text "4.8" at 12660.85,7079.94 h60
  text "5" at 9811.59,6959.94 h60
  text "Bottom Layer" at 10221.51,6959.94 h60
  text "Copper" at 11151.25,6959.94 h60
  text "1.40mil" at 12011.02,6959.94 h60
  text "6" at 9811.59,6839.94 h60
  text "Bottom Solder" at 10221.51,6839.94 h60
  text "Solder Resist" at 11151.25,6839.94 h60
  text "0.40mil" at 12011.02,6839.94 h60
  text "3.5" at 12660.85,6839.94 h60
  text "7" at 9811.59,6719.94 h60
  text "Bottom Overlay" at 10221.51,6719.94 h60
  text ".Layer_Name" at 577,-858.49 h60
M13 Component Bodies Top:
  text ".Layer_Name" at 577,-858.49 h60
M14 Component Bodies Bottom:
  text ".Layer_Name" at 577,-858.49 h60
M15 Courtyards Top:
  text ".Layer_Name" at 577,-858.49 h60
M16 Courtyards Bottom:
  text ".Layer_Name" at 577,-858.49 h60
Drill Drawing:
  circle w10: c1923.75,175 r27.63
  lines w10: 1896.12,23.05 1951.38,23.05 1951.38,78.31 1896.12,78.31 1896.12,23.05 ; 1896.12,326.95 1951.38,326.95 1923.75,271.69 1896.12,326.95 ; 1896.12,409.83 1909.94,409.83 1923.75,396.01 1937.56,409.83 1951.38,409.83 1937.56,423.64 1951.38,437.45 1937.56,437.45 1923.75,451.27 1909.94,437.45 1896.12,437.45 1909.94,423.64 1896.12,409.83
  lines w12: 1846.03,-14.24 5077.52,-14.24 ; 1846.03,483.04 5077.52,483.04 ; 2183.89,-138.56 2183.89,607.36 ; 2515.9,-138.56 2515.9,607.36 ; 3152.46,-138.56 3152.46,607.36 ; 3411.6,-138.56 3411.6,607.36 ; 3786.76,-138.56 3786.76,607.36 ; 4511.09,-138.56 4511.09,607.36 ; 1846.03,-138.56 5077.52,-138.56 5077.52,607.36 1846.03,607.36 1846.03,-138.56
  text "Symbol" at 1920.62,520.33 h72
  text "Quantity" at 2221.19,520.33 h72
  text "Finished Hole Size" at 2553.19,520.33 h72
  text "Plated" at 3189.75,520.33 h72
  text "Hole Type" at 3448.9,520.33 h72
  text "Drill Layer Pair" at 3824.05,520.33 h72
  text "Hole Tolerance" at 4548.38,520.33 h72
  text "1" at 2221.19,396.01 h60
  text "14.00mil (0.356mm)" at 2553.19,396.01 h60
  text "PTH" at 3189.75,396.01 h60
  text "Round" at 3448.9,396.01 h60
  text "Top Layer - Bottom Layer" at 3824.05,396.01 h60
  text "6" at 2221.19,271.69 h60
  text "20.00mil (0.508mm)" at 2553.19,271.69 h60
  text "PTH" at 3189.75,271.69 h60
  text "Round" at 3448.9,271.69 h60
  text "Top Layer - Bottom Layer" at 3824.05,271.69 h60
  text "1" at 2221.19,147.37 h60
  text "28.00mil (0.711mm)" at 2553.19,147.37 h60
  text "PTH" at 3189.75,147.37 h60
  text "Round" at 3448.9,147.37 h60
  text "Top Layer - Bottom Layer" at 3824.05,147.37 h60
  text "4" at 2221.19,23.05 h60
  text "39.37mil (1.000mm)" at 2553.19,23.05 h60
  text "PTH" at 3189.75,23.05 h60
  text "Round" at 3448.9,23.05 h60
  text "Top Layer - Bottom Layer" at 3824.05,23.05 h60
  text "12 Total" at 2221.19,-101.27 h60
  text ".Layer_Name" at 577,-858.49 h60
M17 Embedded Cavity:
  text ".Layer_Name" at 577,-858.49 h60
M18 Embedded Assembly:
  text ".Layer_Name" at 577,-858.49 h60
M19 Embedded Keepout:
  text ".Layer_Name" at 577,-858.49 h60

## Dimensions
0,-400 to 1000,-400 on M2 Board Dimensions
0,1300 to 1150,0 on M2 Board Dimensions
1150,0 to 0,1300 on M2 Board Dimensions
